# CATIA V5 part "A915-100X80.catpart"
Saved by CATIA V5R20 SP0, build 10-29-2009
Part number: A915-100X80
Source: Unknown
Property "A": "50.000"
Property "ARTICLENO": "A915-100X80"
Property "BOMINFO": "A915-100X80"
Property "CODE": "A915-100X80"
Property "CREATOR": "CADENAS GmbH"
Property "D": "13.500"
Property "D1": "20.000"
Property "FORM": "A"
Property "L": "80.000"
Property "L1": "40.000"
Property "L2": "0.000"
Property "LINA": "A915-100X80"
Property "NB": "A915-100X80"
Property "NBSYN": "$CODE."
Property "NN": "A915"
Property "NT": "VDI 3357 Wear Plates, steel"
Property "SCREW": "M12x25"
Property "SUPPLIER": "CF"
Property "T": "13.000"
Property "W": "100.000"
Bounding box of the stored display mesh (mm): x 0 to 20, y 0 to 80, z -50 to 50
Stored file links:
  C:\Users\borellobunino\Desktop\3D X SITO CF\A915\GSB_OILLESS_G22501100080\CATIAV5\A915-100X80.catpart
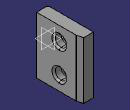
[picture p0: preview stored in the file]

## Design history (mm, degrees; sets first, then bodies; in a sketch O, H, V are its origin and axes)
Body1 "Geometry.1" (main body)
  Solid1 "A915-100X80.catpart": solid without history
